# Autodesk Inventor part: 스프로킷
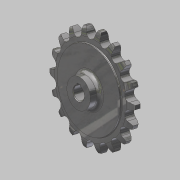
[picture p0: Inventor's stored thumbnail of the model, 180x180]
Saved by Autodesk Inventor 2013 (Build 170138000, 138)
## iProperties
Created: 2016-03
Part Number: 스프로킷
Material: 강철, 탄소
Document SubType Name: Modeling
Designer: mduedu
Density: 7.87 g/cm^3
Author: mduedu
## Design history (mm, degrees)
sketch "스케치1"
  geometry: L1 (0, 5)-(29.5, 5); L2 (29.5, 5)-(29.5, 4.1); L3 (30, 3.6)-(33.625, 3.6); L4 (40, 2)-(40, 0); L5 (40, 0)-(0, 0); L6 (0, 0)-(0, 5); L7 (0, -5)-(29.5, -5); L8 (29.5, -5)-(29.5, -4.1); L9 (30, -3.6)-(33.625, -3.6); L10 (40, -2)-(40, 0); L11 (0, 0)-(0, -5); A1 r 13.5 centre (33.625, -9.9) between (40, 2) and (33.625, 3.6); A2 r 13.5 centre (33.625, 9.9) between (33.625, -3.6) and (40, -2); A3 r 0.5 centre (30, 4.1) between (29.5, 4.1) and (30, 3.6); A4 r 0.5 centre (30, -4.1) between (30, -3.6) and (29.5, -4.1); 2 further points
  constraints: 22 end point, 8 point on circle, 6 symmetric about line, 5 tangent, 4 centre point, 4 parallel, 4 point on line, 1 equal radius, 1 horizontal, 1 perpendicular, 1 other
  dimensions: "d0" = 80 diameter of L4 L6; "d2" = 59 diameter of L2 L6; "d3" = 1.6 vertical distance of L4.start L3.end; "d4" = 3.6 distance from line of L4.end L3; "d5" = 5 distance between parallel lines of L5 L1; "d6" = 13.5 radius of A1; "d15" = 0.5 radius of A3
revolve "회전1" sketch "스케치1" stored, may be unused: angle "d7" = 90 deg
sketch "스케치2" dims "d8" = 65.2, "d11" = 80
  geometry: L1 (0, 0)-(0, 32.6); A1 r 36.57 centre (0, 0) between (-16.231, 32.771) and (0, 36.57); A2 r 3.97 centre (0, 36.57) between (-3.866, 35.665) and (0, 32.6); A3 r 12.7 centre (-16.231, 32.771) between (-3.866, 35.665) and (-5.534, 39.615); A4 r 12.7 centre (16.231, 32.771) between (5.534, 39.615) and (3.866, 35.665); A5 r 3.97 centre (0, 36.57) between (0, 32.6) and (3.866, 35.665); A6 r 40 centre (0, 0) between (5.534, 39.615) and (-5.534, 39.615); 2 further points
  constraints: 12 point on circle, 6 centre point, 4 coincident, 3 symmetric about line, 2 end point, 1 point on line, 1 tangent, 1 vertical, 1 vertical alignment, 7 other
  dimensions: "d10" = 73.14 diameter of A1; "d12" = 12.7 radius of A3
extrude "돌출1" cut sketch "스케치2" stored distance "d13" = 10; taper "d14" = 0 deg
sketch "스케치3"
  geometry: C1 r 11 at (0, 0); 1 further point
  constraints: 1 centre point, 1 coincident
  dimensions: "d19" = 22 diameter of C1
extrude "돌출2" join sketch "스케치3" distance "d20" = 8; taper "d21" = 0 deg
fillet "모깎기1" dims "d22" = 3
sketch "스케치4"
  geometry: L1 (-1.5, 0)-(1.5, 0); L2 (1.5, 0)-(1.5, 6.4); L3 (1.5, 6.4)-(-1.5, 6.4); L4 (-1.5, 6.4)-(-1.5, 0); C1 r 5 at (0, 0); 2 further points
  constraints: 8 end point, 2 coincident, 2 parallel, 1 centre point, 1 horizontal, 1 midpoint, 1 perpendicular
  dimensions: "d23" = 10 diameter of C1; "d25" = 3 distance of L2.end L3.end; "d26" = 6.4 distance of L1.end L2.end
extrude "돌출3" cut sketch "스케치4" stored distance "d27" = 8; taper "d28" = 0 deg
chamfer "모따기1" distance "d29" = 0.5; stored, may be unused: second distance "d30" = 2, angle "d31" = 45 deg
node "솔리드1"
pattern_circular "원형 패턴1" dims angle "d17" = 360 deg
